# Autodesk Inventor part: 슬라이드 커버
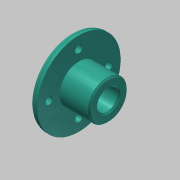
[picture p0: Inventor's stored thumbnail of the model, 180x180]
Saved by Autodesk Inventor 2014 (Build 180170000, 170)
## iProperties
Created: 2015-12
Part Number: 슬라이드 커버
Document SubType Name: Modeling
Designer: mdu
Density: 2.71 g/cm^3
Material: 알루미늄 6061
Mass: 49.5251 g
Surface Area: 80.5945 cm^2
Volume: 18.2749 cm^3
Appearance: 알루미늄 - 평지
Author: mdu
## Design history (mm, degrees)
sketch "스케치1"
  geometry: L1 (-12.5, 0)-(12.5, 0); L2 (-12.5, 0)-(-12.5, 28); L3 (-12.5, 28)-(-7.5, 28); L4 (-7.5, 28)-(-7.5, 13); L5 (-7.5, 13)-(12.5, 13); L6 (12.5, 13)-(12.5, 0); 2 further points
  constraints: 12 end point, 3 perpendicular, 1 coincident, 1 horizontal, 1 midpoint, 1 parallel
  dimensions: "d1" = 56 diameter of L3 L1; "d2" = 26 diameter of L5 L1; "d5" = 5 distance of L2.end L3.end; "d32" = 20 distance of L4.end L5.end
revolve "회전1" sketch "스케치1" stored, may be unused: angle "d6" = 90 deg
sketch "스케치2" dims "d33" = 40
  geometry: 3 further points
  constraints: 2 vertical alignment, 1 coincident, 2 other
hole "구멍1" sketch "스케치2" at (0, 20) diameter "d8" = 5; stored, may be unused: countersink angle "d12" = 90 deg, drill point angle "d14" = 118 deg; dims "d9" = 6, "d10" = 8, "d11" = 4.4, "d13" = 8
hole "구멍2" diameter "d20" = 14; stored, may be unused: countersink angle "d24" = 90 deg, drill point angle "d26" = 0 deg; dims "d18" = 10, "d19" = 10, "d21" = 6, "d22" = 8, "d23" = 4.4, "d25" = 8
fillet "모깎기1" dims "d27" = 3
chamfer "모따기1" distance "d29" = 1; stored, may be unused: second distance "d30" = 2, angle "d31" = 45 deg
node "솔리드1"
pattern_circular "원형 패턴1" dims angle "d16" = 360 deg
